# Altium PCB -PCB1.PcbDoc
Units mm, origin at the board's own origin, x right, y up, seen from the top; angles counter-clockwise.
Board outline 80 x 60 mm, 2 copper layers (Top Layer, Bottom Layer); 29 components, 18 nets, 66 pads, 0 vias.
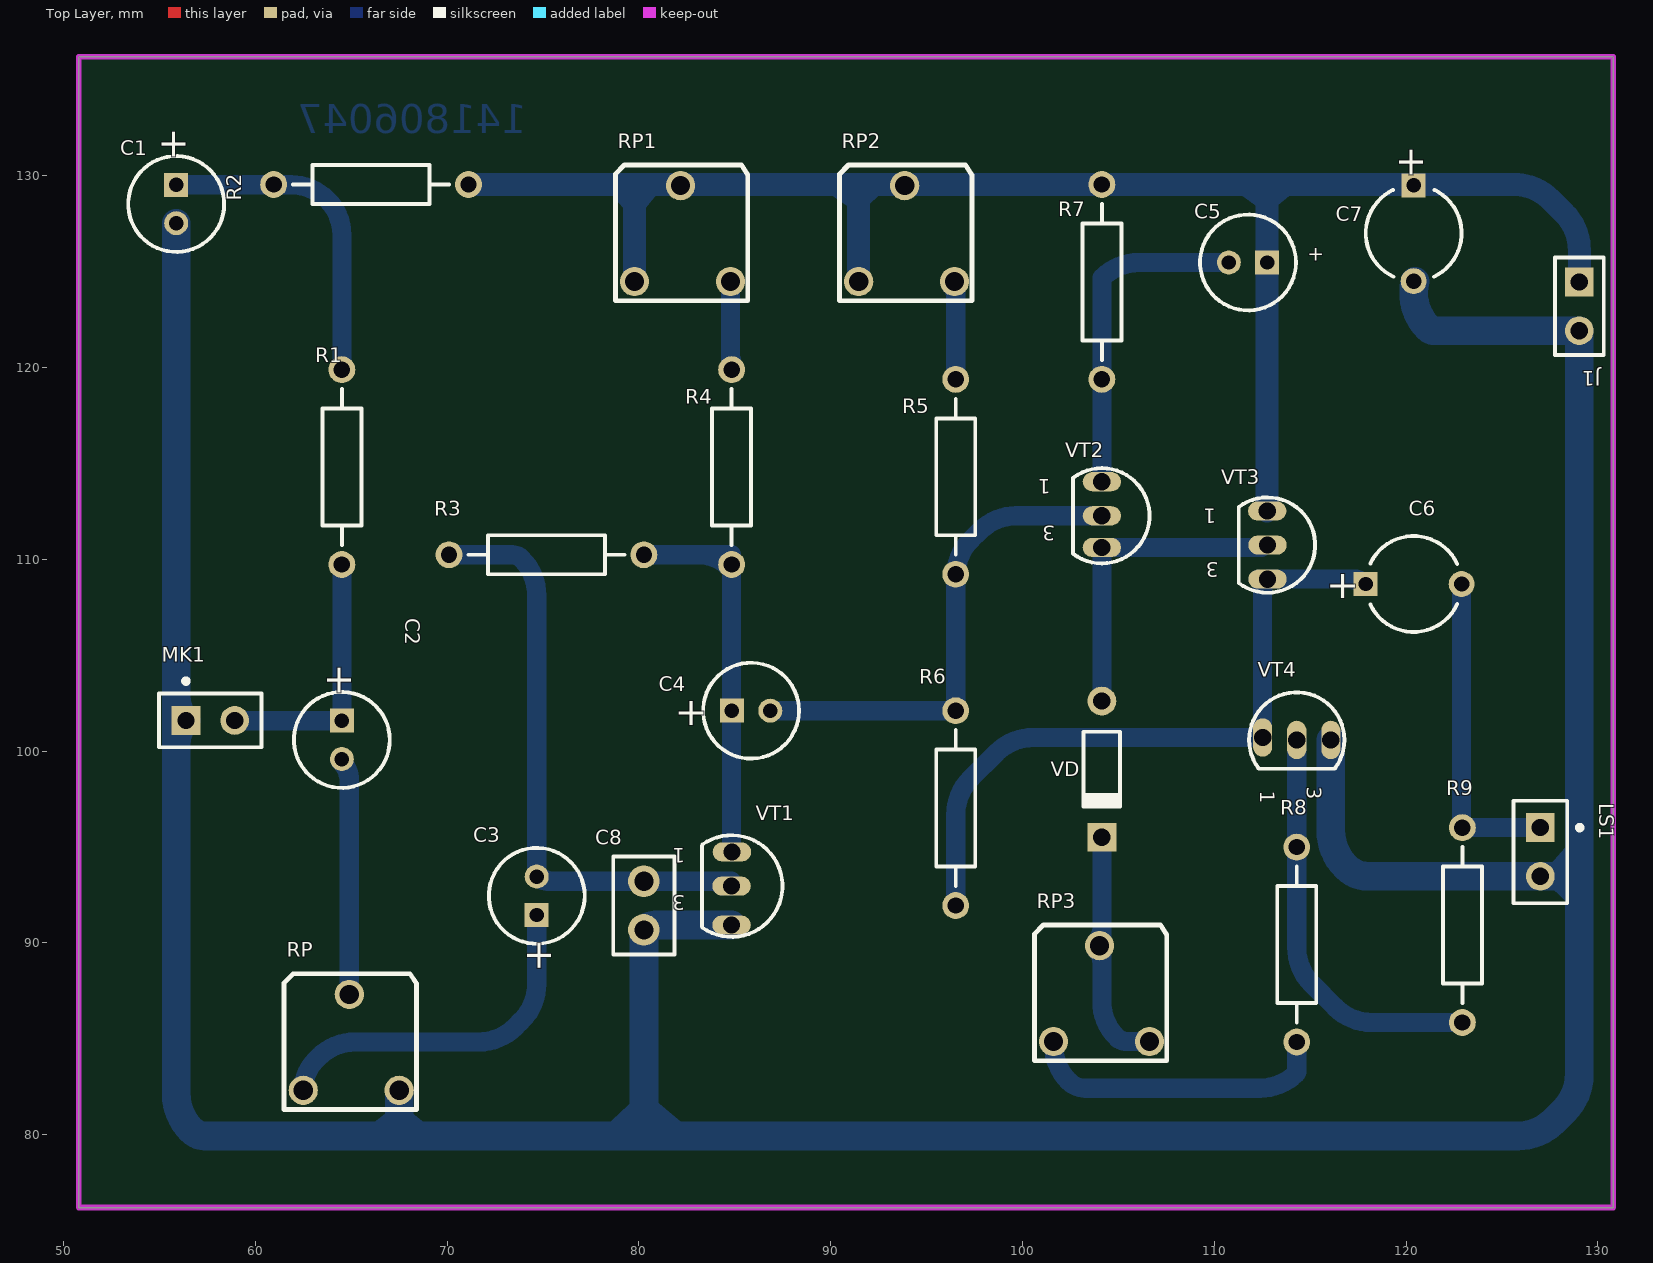
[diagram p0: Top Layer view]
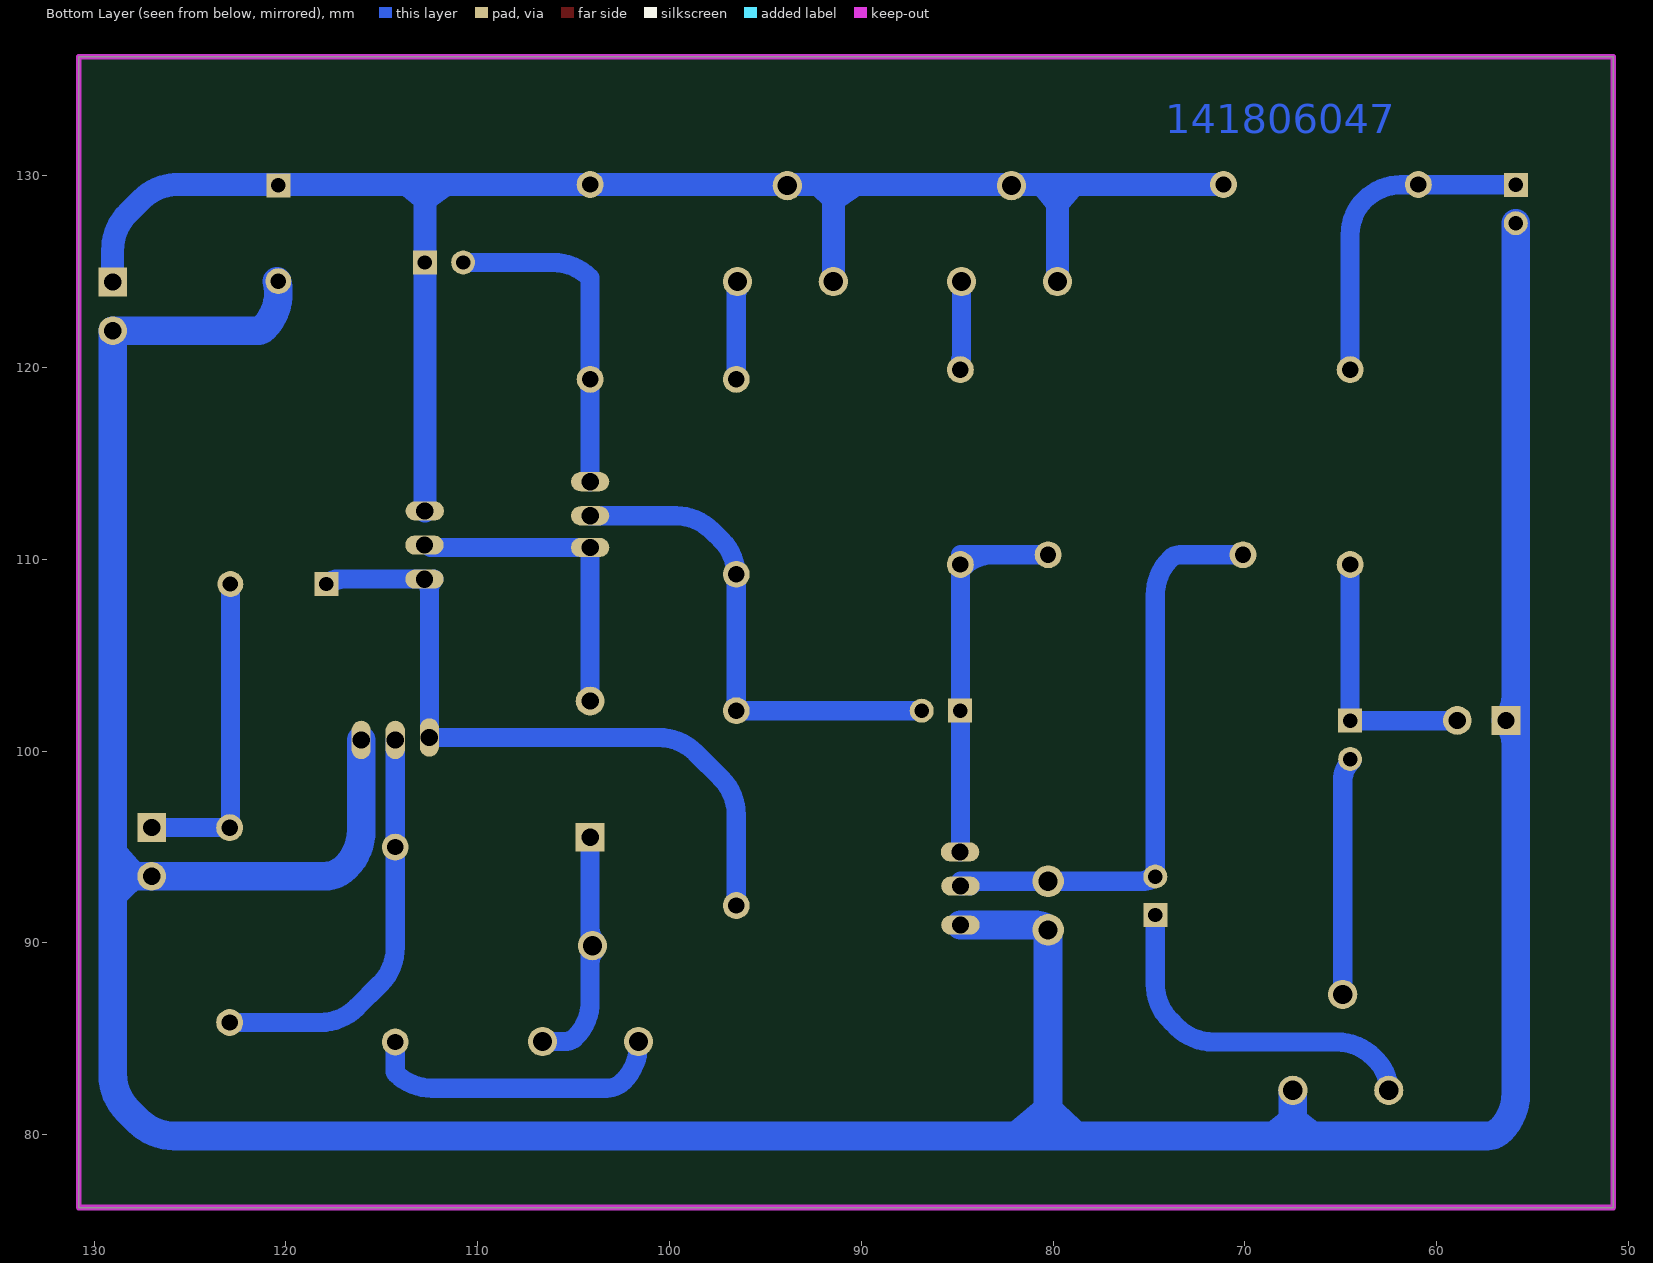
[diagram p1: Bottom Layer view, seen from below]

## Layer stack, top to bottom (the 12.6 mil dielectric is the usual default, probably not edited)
Top Layer: signal copper 0.0356
Dielectric: dielectric 0.32, FR-4, Dk 4.8
Bottom Layer: signal copper 0.0356

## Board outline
50.8,76.2 130.8,76.2 130.8,136.2 50.8,136.2

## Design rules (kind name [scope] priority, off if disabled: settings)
Clearance [All] p1: gap=0.2
ComponentClearance [All] p1: gap=0.254 collisioncheckmode=0
PolygonConnect [All] p1: connectstyle=Relief reliefconductorwidth=0.254 reliefentries=4 polygonreliefangle="90 Angle"
RoutingCorners [All] p1: cornerstyle=Round minsetback=2.54 maxsetback=2.54
RoutingLayers [All] p1: top layer_v5=FALSE bottom layer_v5=TRUE
RoutingVias [All] p1: holewidth=0.6 width=1 viastyle="Through Hole" minholewidth=0.711 minwidth=2 maxholewidth=0.8 maxwidth=1.27
SolderMaskExpansion [All] p1: expansion=0.102
TestPointUsage [All] p1: valid=0 allowmultiple=FALSE
Testpoint [All] p1: side=15 testpointundercomponent=TRUE minsize=1.016 maxsize=2.54 preferedsize=1.524 minholesize=0 maxholesize=1.016 preferedholesize=0.813 testpointgrid=0.025 style=1023 order=1234567890
Width Width_2 [InNet('GND')] p1: maxlimit=1.5 minlimit=1.5 preferedwidth=1.5
Width Width_1 [InNet('VCC')] p2: maxlimit=1.2 minlimit=1.2 preferedwidth=1.2
Width [All] p3: maxlimit=1 minlimit=1 preferedwidth=1
15 further rules are at their usual default settings.

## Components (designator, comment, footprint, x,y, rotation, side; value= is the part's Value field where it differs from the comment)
C1 "Cap Pol1" CAPPR2-5x6.8 55.88,128.524 r270 top
C2 "Cap Pol1" CAPPR2-5x6.8 64.516,100.584 r270 top
C3 "Cap Pol1" CAPPR2-5x6.8 74.676,92.456 r90 top
C4 "Cap Pol1" CAPPR2-5x6.8 85.852,102.108 r0 top
C5 "Cap Pol1" CAPPR2-5x6.8 111.76,125.476 r180 top
C6 "Cap Pol1" CAPPR5-5x5 120.396,108.712 r0 top
C7 "Cap Pol1" CAPPR5-5x5 120.396,127 r270 top
C8 "Cap" CAPR2.54-5.1x3.2 80.264,91.948 r90 top
J1 "MHDR1X2" HDR1X2 129.032,124.46 r270 top
LS1 "Speaker" PIN2 127,96.012 r270 top
MK1 "Mic" PIN2 56.388,101.6 r0 top
R1 "Res2" AXIAL-0.4 64.516,114.808 r90 top
R2 "Res2" AXIAL-0.4 66.04,129.54 r180 top
R3 "Res2" AXIAL-0.4 75.184,110.236 r180 top
R4 "Res2" AXIAL-0.4 84.836,114.808 r270 top
R5 "Res2" AXIAL-0.4 96.52,114.3 r270 top
R6 "Res2" AXIAL-0.4 96.52,97.028 r270 top
R7 "Res2" AXIAL-0.4 104.14,124.46 r270 top
R8 "Res2" AXIAL-0.4 114.3,89.916 r90 top
R9 "Res2" AXIAL-0.4 122.936,90.932 r90 top
RP "RPot" RM065 57.404,89.916 r0 top
RP1 "RPot" RM065 74.676,132.08 r0 top
RP2 "RPot" RM065 86.36,132.08 r0 top
RP3 "RPot" RM065 96.52,92.456 r0 top
VD "4148" DIO7.1-3.9x1.9 104.14,99.06 r270 top
VT1 "9014" BCY-W3 84.836,92.964 r180 top
VT2 "9015" BCY-W3/E4#1 104.14,112.268 r180 top
VT3 "8050" BCY-W3/E4#2 112.776,110.744 r180 top
VT4 "8550" BCY-W3/E4#3 114.3,100.584 r270 top

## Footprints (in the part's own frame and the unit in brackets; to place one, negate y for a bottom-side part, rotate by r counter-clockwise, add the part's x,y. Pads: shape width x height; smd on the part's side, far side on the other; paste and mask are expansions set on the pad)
AXIAL-0.4 [mm] "Resistor; 2 Leads"
  round 1.4 hole 0.85: 1(-5.08,0) 2(5.08,0)
  silkscreen extent -4.06,-1.02 4.06,1.02
BCY-W3 [mm] "TO, Flat Index; 3 In-Line, Axial Leads; Body Dia. 4.8mm"
  oval 2x1 hole 0.9: 1(-0.016,-1.778) 2(0,0) 3(0,2.032)
  silkscreen extent -2.65,-2.65 1.55,2.65
BCY-W3/E4#1 [mm] "TO, Flat Index; 3 In-Line, Axial Leads; Body Dia. 4.7mm"
  oval 2x1 hole 0.9: 1(0,-1.778) 2(0,0) 3(0,1.651)
  silkscreen extent -2.48,-2.48 1.5,2.48
BCY-W3/E4#2 [mm] "TO, Flat Index; 3 In-Line, Axial Leads; Body Dia. 4.7mm"
  oval 2x1 hole 0.9: 1(0.016,-1.778) 2(0,0) 3(0,1.778)
  silkscreen extent -2.48,-2.48 1.5,2.48
BCY-W3/E4#3 [mm] "TO, Flat Index; 3 In-Line, Axial Leads; Body Dia. 4.7mm"
  oval 2x1 hole 0.9: 1(-0.127,-1.778) 2(0,0) 3(0,1.778)
  silkscreen extent -2.48,-2.48 1.5,2.48
CAPPR2-5x6.8 [mm] "Capacitor, Electrolytic, Radial; Body 5 x 6.8 mm (Dia.xH typ); Pin Spacing 2 mm (typ)"
  rect 1.25x1.25 hole 0.75: 1(-1,0)
  round 1.25 hole 0.75: 2(1,0)
  silkscreen extent -2.5,-2.5 2.5,2.5
CAPPR5-5x5 [mm] "Capacitor, Electrolytic, Radial; Body 5 x 5 mm (Dia.xH typ); Pin Spacing 5 mm (typ)"
  rect 1.25x1.25 hole 0.75: 1(-2.5,0)
  round 1.35 hole 0.8: 2(2.5,0)
  silkscreen extent -2.26,-2.5 2.27,2.5
CAPR2.54-5.1x3.2 [mm] "Capacitor, Ceramic, Thru-Hole, Dipped Radial; Body 5.1 x 3.2 mm (WxT) Pin Spacing 2.54 mm (typ)"
  round 1.65 hole 1: 1(-1.27,0) 2(1.27,0)
  silkscreen extent -2.55,-1.6 2.55,1.6
DIO7.1-3.9x1.9 [mm] "Diode, Axial; Body 3.8 x 1.9 mm (LxDia. max), Lead Dia. 0.53 mm (max)"
  round 1.5 hole 0.9: 1(-3.55,0)
  rect 1.5x1.5 hole 0.9: 2(3.55,0)
  silkscreen extent -1.95,-0.95 2.05,0.95
HDR1X2 [mm] "Connector; Header; 2 Position"
  rect 1.5x1.5 hole 0.9: 1(0,0)
  round 1.5 hole 0.9: 2(2.54,0)
  silkscreen extent -1.27,-1.27 3.81,1.27
PIN2 [mm] "Photosensitive Diode; 2 Leads"
  rect 1.5x1.5 hole 0.9: 1(0,0)
  round 1.5 hole 0.9: 2(2.54,0)
  silkscreen extent -1.4,-1.4 3.94,2.18
RM065 [mm]
  round 1.524 hole 1: 1(5.1,-7.6) 2(7.5,-2.6) 3(10.1,-7.6)
  silkscreen extent 4.1,-8.6 11,-1.52

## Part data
C1 C2 C3 C4 C5 C6 C7: "Polarized Capacitor (Radial)"
C8: "Capacitor"
J1: library part "Header 2", "Header, 2-Pin"
LS1: "Loudspeaker"
MK1: library part Mic2, "Microphone"
R1 R2 R3 R4 R5 R6 R7 R8 R9: "Resistor"
RP RP1 RP2 RP3: "Potentiometer"
VD: library part "Diode 1N4148", "High Conductance Fast Diode"
VT1: library part NPN, "NPN Bipolar Transistor"
VT2 VT3 VT4: library part 2N3906, "PNP General Purpose Amplifier"

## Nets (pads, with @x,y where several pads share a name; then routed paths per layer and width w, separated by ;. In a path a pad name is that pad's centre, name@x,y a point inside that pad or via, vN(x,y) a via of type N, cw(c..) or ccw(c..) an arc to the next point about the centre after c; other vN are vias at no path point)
GND: C1.2 C7.2 C8.1 J1.2 LS1.2 MK1.1 RP.3 VT1.3 VT4.3 | length 215
  Bottom Layer w1.5: C1.2 55.88,82.144 ccw(c58.578,82.144) 56.67,80.236 ccw(c57.399,80.965) 56.766,80.151 ccw(c57.399,80.965) 57.399,79.934 125.806,79.934 ccw(c125.806,82.632) 127.714,80.724 128.242,81.252 ccw(c126.334,83.16) 129.032,83.16 J1.2 121.465,121.92 cw(c121.465,122.354) 121.158,122.047 cw(c122.998,123.887) C7.2@120.465,124.484 ; 67.437,79.934 ccw(c67.275,80.096) 67.504,80.096 RP.3 ; 80.264,79.934 C8.1 cw(c80.877,90.065) 80.877,90.932 VT1.3 ; VT4.3 116.078,95.86 ccw(c118.776,95.86) 116.868,93.952 ccw(c118.026,95.11) 118.026,93.472 129.032,93.472 ; MK1.1 ccw(c57.614,100.374) 55.88,100.374 cw(c57.614,100.374) MK1.1 ; MK1.1 cw(c57.614,102.826) 55.88,102.826 ccw(c57.614,102.826) MK1.1 ; C8.1@80.317,90.625 cw(c81.058,89.884) 81.058,90.932 ccw(c81.058,89.884) C8.1@80.317,90.625
NetC1_1: C1.1 R1.2 R2.2 | length 17.1
  Bottom Layer w1: C1.1 61.86,129.524 cw(c61.86,126.826) 63.767,128.734 cw(c61.96,126.927) 64.516,126.927 R1.2
NetC2_1: C2.1 MK1.2 R1.1 | length 13.7
  Bottom Layer w1: MK1.2@58.967,101.584 C2.1 R1.1
NetC2_2: C2.2 RP.2 | length 16
  Bottom Layer w1: RP.2 64.904,98.647 ; C2.2@64.428,99.496 cw(c63.277,98.345) 64.904,98.345 ccw(c63.277,98.345) C2.2@64.428,99.496 ; C2.2@64.442,99.483 cw(c63.771,98.57) 64.904,98.57 ccw(c63.771,98.57) C2.2@64.442,99.483
NetC3_1: C3.1 RP.1 | length 18.8
  Bottom Layer w1: RP.1 cw(c64.755,82.316) 63.163,83.908 63.301,84.046 cw(c65.209,82.138) 65.209,84.836 71.653,84.836 ccw(c71.653,87.534) 73.561,85.626 73.886,85.951 ccw(c71.978,87.859) 74.676,87.859 C3.1
NetC3_2: C3.2 C8.2 R3.2 VT1.2 | length 34.6
  Bottom Layer w1: R3.2 73.393,110.236 cw(c73.393,109.54) 73.886,110.032 cw(c71.978,108.124) 74.676,108.124 C3.2 ccw(c75.251,94.031) 75.251,93.218 VT1.2@84.836,93.218 ; VT1.2@84.223,93.218 ccw(c84.836,93.831) VT1.2 ; C3.2@74.764,93.544 ccw(c75.552,94.332) 75.552,93.218 cw(c75.552,94.332) C3.2@74.764,93.544 ; 83.723,93.218 cw(c83.723,92.351) 84.336,92.964 ccw(c83.723,92.351) 83.723,93.218
NetC4_1: C4.1 R3.1 R4.2 VT1.1 | length 21.8
  Bottom Layer w1: R3.1 84.836,110.236 84.836,94.781 ccw(c84.891,94.781) VT1.1 ; 83.127,110.236 cw(c83.127,108.019) R4.2@84.695,109.587
NetC4_2: C4.2 R5.2 R6.1 VT2.2 | length 26
  Bottom Layer w1: C4.2 R6.1 96.52,109.109 cw(c99.218,109.109) 97.31,111.017 97.771,111.478 cw(c99.679,109.57) 99.679,112.268 VT2.2
NetC5_2: C5.2 R7.2 VT2.1 | length 17.5
  Bottom Layer w1: VT2.1 104.14,124.627 cw(c104.223,124.627) 104.164,124.686 cw(c106.072,122.778) 106.072,125.476 C5.2
NetC6_1: C6.1 R6.2 VT3.3 VT4.1 | length 38.6
  Bottom Layer w1: R6.2 96.52,96.672 cw(c99.218,96.672) 97.31,98.58 98.651,99.921 cw(c100.559,98.013) 99.123,100.298 cw(c100.559,98.013) 100.559,100.711 VT4.1 112.522,108.353 cw(c113.389,108.353) VT3.3 117.283,108.966 cw(c117.283,108.099) C6.1 ; 116.981,108.966 cw(c116.981,107.797) C6.1@117.808,108.624 ; VT3.3@112.276,108.966 cw(c111.682,108.372) 112.522,108.372 ccw(c111.682,108.372) VT3.3@112.276,108.966
NetC6_2: C6.2 LS1.1 R9.2 | length 16.8
  Bottom Layer w1: C6.2 122.896,96.109 ccw(c123.033,96.109) R9.2 LS1.1
NetR4_1: R4.1 RP1.3 | length 4.1
  Bottom Layer w1: RP1.3 84.776,120.541 ccw(c84.981,120.541) R4.1@84.836,120.396
NetR5_1: R5.1 RP2.3 | length 5.6
  Bottom Layer w1: RP2.3@96.275,124.295 cw(c95.683,123.703) 96.52,123.703 ; R5.1 RP2.3@96.52,124.335
NetR8_1: R8.1 RP3.1 | length 15.9
  Bottom Layer w1: RP3.1@101.62,84.694 ccw(c104.318,84.694) 102.41,82.787 ccw(c103.288,83.664) 103.288,82.423 112.368,82.423 ccw(c112.368,85.121) 114.276,83.213 ; 114.3,83.272 R8.1
NetR8_2: R8.2 R9.1 VT4.2 | length 21.4
  Bottom Layer w1: VT4.2 114.3,89.764 ccw(c116.998,89.764) 115.09,87.856 116.304,86.642 ccw(c118.212,88.55) 118.212,85.852 ; 118.29,85.852 R9.1
NetRP3_2: RP3.2 RP3.3 VD.2 | length 15.7
  Bottom Layer w1: VD.2 104.14,86.93 ccw(c106.742,86.93) 104.902,85.09 ccw(c105.467,85.655) 105.467,84.856 RP3.3 ; RP3.2@103.835,89.671 cw(c103.098,88.934) 104.14,88.934 ccw(c103.098,88.934) RP3.2@103.835,89.671 ; RP3.2@103.835,90.041 ccw(c103.098,90.778) 104.14,90.778 cw(c103.098,90.778) RP3.2@103.835,90.041
NetVD_1: VD.1 VT2.3 VT3.2 | length 16.3
  Bottom Layer w1: VD.1 VT2.3 VT3.2@112.469,110.617
VCC: C5.1 C7.1 J1.1 R2.1 R7.1 RP1.1 RP1.2 RP2.1 RP2.2 VT3.1 | length 87.7
  Bottom Layer w1.2: R2.1 79.756,129.54 ; RP1.1 79.776,128.975 ; 80.01,129.54 125.628,129.54 cw(c125.628,126.842) 126.011,129.513 cw(c125.628,126.842) 127.536,128.75 128.242,128.044 cw(c126.334,126.136) 129.005,126.519 cw(c126.334,126.136) 129.032,126.136 J1.1 ; RP2.1 91.46,129.492 ; VT3.1 112.76,129.501

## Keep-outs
Keep-Out Layer:
  the board outline again, w0.3

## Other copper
Bottom Layer:
  region net VCC: 112.76,128.016 114.173,129.159 110.998,129.286
  region net VCC: 91.46,128.016 92.71,129.159 89.789,129.159
  region net VCC: 79.776,127.635 81.153,129.286 78.359,129.286
  region net GND: 80.264,82.296 82.677,80.264 78.232,80.391
  region net GND: 67.504,81.661 69.088,80.391 66.04,80.518
  region net GND: 127,93.472 128.651,91.821 128.651,95.377
  text "141806047" at 74.168,132.207 h1.52

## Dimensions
50.8,76.2 to 50.8,136.2 on Mechanical 1
50.8,76.2 to 130.8,76.2 on Mechanical 1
